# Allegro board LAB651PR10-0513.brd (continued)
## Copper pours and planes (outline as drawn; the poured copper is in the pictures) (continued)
DH_CHG on BOTTOM (solid shape): 43.74,18.65 43.74,17.68 43.57,17.5 43.57,16.51 43.54,16.49 43.34,16.49 43.31,16.51 43.31,17.56 43.21,17.66 43.21,18.67 43.29,18.75 43.64,18.75
DL_1.35V on BOTTOM (solid shape): 88.45,21.01 88.45,20.12 88.32,19.99 87.43,19.99 87.31,20.12 87.31,21.01 87.43,21.14 88.32,21.14
DL_1.35V on BOTTOM (solid shape): 86.04,14.41 86.04,13.39 84.89,12.25 84.77,12.25 84.64,12.37 84.64,13.39 85.78,14.53 85.91,14.53
DL_1.35V on IN1 (solid shape): 86.16,14.41 86.16,14.03 85.4,13.26 85.02,13.26 84.89,13.39 84.89,14.03 85.53,14.66 85.91,14.66
DL_1.35V on IN1 (solid shape): 88.7,21.26 88.7,20.07 88.5,19.87 87.53,19.87 87.31,20.1 87.31,21.26 87.43,21.39 88.58,21.39
DL_CHG on TOP (solid shape): 36.63,23.42 36.63,22.28 36.51,22.15 35.43,22.15 35.24,22.34 35.24,23.36 35.36,23.49 36.57,23.49
DL_CHG on BOTTOM (solid shape): 40.1,15.83 40.17,15.72 40.28,15.65 40.35,15.58 40.62,15.58 40.74,15.45 41.81,15.45 41.84,15.42 41.84,15.21 41.83,15.2 40.53,15.2 40.51,15.22 38.91,15.22 38.83,15.31 38.83,15.92 38.94,16.03 39.89,16.03
DL_CHG on IN1 (solid shape): 38.71,16.31 39.81,16.31 40.06,16.06 40.06,15.55 39.79,15.28 38.31,15.28 37.58,16.01 37.58,16.44 38.58,16.44
DL_CHG on IN1 (solid shape): 37.65,21.77 37.65,21.39 37.14,20.88 37.01,20.88 36,21.9 34.85,21.9 34.73,22.03 34.73,22.66 34.98,22.92 36.51,22.92
DP_VSSR on TOP (solid shape): 75.49,86.29 75.49,85.42 75.49,85.31 75.49,78.16 75.24,77.91 73.78,77.91 73.46,78.23 73.46,81.46 73.21,81.72 72.45,81.72 72.32,81.59 72.32,81.28 72.29,81.25 72.29,81.18 72.19,81.08 72.12,81.08 72.12,81.11 71.66,81.11 71.56,81.21 71.56,82.22 71.81,82.48 71.81,84.89 72.45,85.53 72.45,86.42 72.56,86.53 73.15,86.53 73.15,86.54 75.24,86.54
EN_PCIE on BOTTOM (solid shape): 76.56,56.65 76.56,56.01 76.76,55.81 77.4,55.81 77.78,55.43 77.78,55.05 77.65,54.92 75.88,54.92 75.37,55.43 74.99,55.43 74.86,55.55 74.86,56.57 74.99,56.7 76.51,56.7
FB on TOP (solid shape): 61.78,120.45 61.78,119.82 61.91,119.69 62.54,119.69 62.67,119.56 62.67,118.22 62.49,118.04 61.27,118.04 61.14,118.17 61.14,120.45 61.27,120.58 61.65,120.58
FB_1.1V on BOTTOM (solid shape): 112.2,4.63 112.2,3.1 111.82,2.72 108.31,2.72 108.22,2.81 108.22,3.36 108.48,3.61 110.55,3.61 110.93,3.99 110.93,4.48 111.2,4.75 112.07,4.75
FB_1.5V on TOP (solid shape): 209.99,12.12 209.99,9.83 209.86,9.71 207.83,9.71 207.57,9.96 207.57,10.47 208.18,11.08 208.2,11.08 208.54,11.41 208.25,11.78 208.21,11.79 208.21,11.87 208.59,12.25 209.86,12.25
GPU_B+ on TOP (solid shape): 71.02,45.52 74.22,45.52 74.67,45.07 74.67,43.05 73.78,42.16 67.18,42.16 66.48,42.85 61.86,42.85 61.7,42.7 60.43,42.7 60.2,42.47 60.2,41.52 60.1,41.42 55.79,41.42 55.68,41.43 55.58,41.42 51.95,41.42 51.49,41.87 51.49,45.45 52.11,46.07 57.13,46.07 57.21,46.16 64.45,46.16 64.7,46.41 64.7,47.17 64.95,47.43 69.12,47.43
GPU_B+ on BOTTOM (solid shape): 66.2,45.92 66.2,44.49 65.69,43.97 57.21,43.97 56.95,44.23 56.95,45.9 57.21,46.16 65.97,46.16
INT-SPK-L+ on TOP (solid shape): 203.92,17.07 203.92,16.02 203.83,15.93 202.24,15.93 202.11,16.06 202.11,16.95 202.32,17.15 203.84,17.15
INT-SPK-L+ on BOTTOM (solid shape): 202.04,20.02 202.04,19.69 201.93,19.58 199.24,19.58 199.24,19.79 200.82,19.79 201.12,20.1 201.96,20.1
INT-SPK-L+ on IN1 (solid shape): 203.54,16.39 202.95,15.8 201.78,15.8 201.61,15.98 201.61,17.1 202.85,18.34 203.54,18.34
INT-SPK-L+ on IN1 (solid shape): 202.37,20.12 202.49,20.12 203,19.61 203,19.23 202.62,18.85 202.37,18.85 201.89,19.33 201.83,19.33 201.81,19.35 201.58,19.46 201.33,19.38 201.26,19.36 201.2,19.38 201.06,19.45 200.91,19.46 200.88,19.45 200.77,19.56 200.77,19.84 200.94,20.07 200.88,20.35 200.86,20.39 201.17,20.71 201.78,20.71
INT-SPK-L- on TOP (solid shape): 206.58,16.92 206.58,15.07 206.47,14.95 205.15,14.95 205.04,15.06 205.04,16.95 205.25,17.16 206.34,17.16
INT-SPK-L- on BOTTOM (solid shape): 201.81,19.31 201.81,18.95 201.73,18.88 200.87,18.88 200.56,19.18 199.33,19.18 199.33,19.39 201.73,19.39
INT-SPK-L- on IN2 (solid shape): 206.91,15.8 206.79,15.68 206.05,15.68 205.9,15.83 205.9,18.01 206.91,18.01
INT-SPK-L- on IN2 (solid shape): 200.92,19.66 201.2,19.51 201.49,19.64 201.51,19.66 201.56,19.66 201.57,19.65 201.81,19.57 202.03,19.66 202.27,19.66 202.47,19.46 202.47,18.88 202.24,18.65 201.91,18.65 201.66,18.82 201.36,18.73 201.29,18.7 201.22,18.73 201.03,18.82 200.81,18.79 200.71,18.79 200.67,18.88 200.67,19.51 200.82,19.66
INT-SPK-R+ on TOP (solid shape): 207.52,17.17 208.76,17.17 208.84,17.09 208.84,16.06 208.72,15.93 207.32,15.93 207.09,16.16 207.09,17.2 207.18,17.29 207.41,17.29
INT-SPK-R+ on BOTTOM (solid shape): 200.78,18.06 201.75,18.06 201.85,17.96 201.85,17.66 201.77,17.58 200.9,17.58 200.09,18.38 199.51,18.38 199.47,18.42 199.47,18.53 199.53,18.59 200.26,18.59
INT-SPK-R+ on IN3 (solid shape): 207.83,17.84 207.83,16.08 207.65,15.9 206.97,15.9 206.81,16.06 206.81,16.97 206.3,17.48 206.3,18.22 207.45,18.22
INT-SPK-R+ on IN3 (solid shape): 203.79,17.53 203.79,16.74 203.74,16.69 203.16,16.69 202.62,17.23 201.68,17.23 201.33,17.58 200.84,17.58 200.74,17.68 200.74,17.99 200.82,18.06 203.26,18.06
INT-SPK-R- on TOP (solid shape): 212.4,16.95 212.4,15.43 212.25,15.28 210.09,15.28 209.86,15.51 209.86,16.95 210.09,17.17 212.17,17.17
INT-SPK-R- on BOTTOM (solid shape): 200.79,18.7 201.78,18.7 201.83,18.64 201.83,18.36 201.71,18.24 200.88,18.24 200.33,18.78 199.46,18.78 199.45,18.8 199.45,18.98 199.46,18.99 200.5,18.99
INT-SPK-R- on IN3 (solid shape): 212.65,17.68 212.65,15.68 212.53,15.55 211.79,15.55 211.64,15.7 211.64,17.78 212.55,17.78
INT-SPK-R- on IN3 (solid shape): 204.43,18.9 203.76,18.24 200.87,18.24 200.74,18.37 200.74,18.6 200.84,18.7 202.06,18.7 203.1,19.74 204.43,19.74
LG_3V on TOP (solid shape): 69.69,19.93 69.69,19.92 70.59,19.03 71.22,19.03 71.29,18.97 71.29,18.9 71.22,18.84 69.93,18.84 68.91,19.85 68.91,20.16 69.04,20.29 69.34,20.29
LG_5V on TOP (solid shape): 63.73,17.38 63.73,16.62 63.68,16.57 63.68,16.06 63.18,15.55 62.54,15.55 62.29,15.8 62.29,16.95 62.3,16.96 62.3,17.42 62.46,17.59 63.52,17.59
LG_5V on TOP (solid shape): 71.29,17.39 71.29,17.25 71.22,17.19 70.84,17.19 70.45,16.79 70.45,16.46 69.9,15.92 69.47,15.92 69.37,16.02 69.37,16.3 69.37,16.32 69.38,16.33 69.42,16.38 69.46,16.44 70.23,17.21 70.22,17.23 70.22,17.33 70.33,17.44 71.24,17.44
LG_5V on IN3 (solid shape): 70.54,16.82 70.54,16.31 69.44,15.21 68.98,15.21 68.57,15.61 69.94,16.97 70.39,16.97
LG_5V on IN3 (solid shape): 63.23,16.7 63.23,16.26 63.81,15.68 63.81,15.42 63.43,15.04 63.05,15.04 62.36,15.73 62.36,16.78 62.44,16.86 63.07,16.86
LG_+1.05VSP on TOP (solid shape): 180.24,45.57 180.24,44.78 180.12,44.66 180.02,44.66 179.79,44.43 179.79,43.74 179.66,43.62 179.33,43.62 179.25,43.69 179.25,45.42 179.56,45.72 180.09,45.72
LG_+1.05VSP on BOTTOM (solid shape): 181.29,51.62 181.29,50.73 181.16,50.6 180.6,50.6 180.35,50.86 180.35,51.54 180.45,51.64 180.8,51.64 180.9,51.74 181.16,51.74
LG_+1.05VSP on IN3 (solid shape): 181.54,51.74 181.54,49.2 180.52,49.2 180.52,51.74 180.78,52 181.29,52
LG_+1.05VSP on IN3 (solid shape): 180.17,43.59 179.91,43.34 179.23,43.34 179,43.57 179,45.19 179.15,45.34 179.15,45.98 180.17,45.98
LG_+1.35VGPUP on TOP (solid shape): 41.51,49.37 41.51,48.78 41.31,48.57 39.88,48.57 39.68,48.77 39.68,49.59 39.81,49.71 41.17,49.71
LGATE1 on TOP (solid shape): 60.38,54.87 60.38,54.16 60.64,53.9 60.64,53.52 60.51,53.4 59.37,53.4 59.11,53.65 59.11,53.9 59.29,54.08 59.59,54.08 59.75,54.23 59.75,54.87 59.85,54.97 60.28,54.97
LGATE1 on BOTTOM (solid shape): 61.4,42.47 61.4,41.46 61.02,41.08 61.02,38.66 60.89,38.66 60.76,38.79 60.76,40.82 60.25,41.33 60.25,42.47 60.38,42.6 61.27,42.6
LGATE1 on IN3 (solid shape): 60.69,53.84 60.69,53.17 60.28,52.76 60,52.76 59.26,53.5 59.26,53.93 59.41,54.08 60.45,54.08
LGATE1 on IN3 (solid shape): 61.22,42.47 61.22,41.43 60.97,41.18 60.64,41.18 60.33,41.48 60.33,42.47 60.51,42.65 61.04,42.65
LGATE2 on TOP (solid shape): 62.79,48.68 62.79,48.24 63.07,47.96 63.07,47.63 62.95,47.5 62.06,47.5 61.91,47.65 61.91,48.62 62.02,48.73 62.74,48.73
LGATE2 on BOTTOM (solid shape): 62.92,42.6 62.92,40.7 62.29,40.06 62.29,38.79 62.16,38.66 62.03,38.79 62.03,40.31 62.29,40.57 62.29,41.46 61.78,41.97 61.78,42.6 61.91,42.73 62.79,42.73
LGATE2 on IN3 (solid shape): 63.07,48.02 63.07,47.35 62.49,46.77 61.4,46.77 61.4,47.66 62.02,48.29 62.81,48.29
LGATE2 on IN3 (solid shape): 62.16,43.67 62.79,43.03 62.79,41.76 62.62,41.58 62.21,41.58 62.03,41.76 62.03,42.68 61.4,43.31 61.4,44.07 61.45,44.12 62.16,44.12
LGATE_APU1 on TOP (solid shape): 68,115.6 68,114.79 67.27,114.05 66.12,114.05 66.12,114.25 66.96,114.25 67.44,114.74 67.44,115.6 67.57,115.73 67.87,115.73
LGATE_APU1 on BOTTOM (solid shape): 88.7,120.2 88.7,119.44 88.58,119.31 86.42,119.31 86.29,119.44 86.29,120.2 86.42,120.32 88.58,120.32
LGATE_APU1 on IN3 (solid shape): 68.21,114.46 68.05,114.3 67.37,114.3 67.19,114.48 67.19,116.82 68.21,116.82
LGATE_APU1 on IN3 (solid shape): 87.56,120.32 88.7,120.32 88.83,120.2 88.83,119.44 88.58,119.18 87.18,119.18 85.78,120.58 85.78,121.34 85.91,121.47 86.42,121.47
LGATE_NB1 on TOP (solid shape): 68.48,112.58 68.48,112.32 68.33,112.17 67.49,112.17 67.21,112.45 66.17,112.45 66.15,112.48 66.15,112.63 66.17,112.65 66.86,112.65 66.91,112.7 68.36,112.7
LGATE_NB1 on BOTTOM (solid shape): 80.96,109.91 80.96,109.15 80.83,109.02 78.8,109.02 78.67,109.15 78.67,109.91 78.8,110.04 80.83,110.04
LGATE_NB1 on IN3 (solid shape): 80.19,109.91 80.96,109.91 81.21,109.66 81.21,109.02 81.08,108.89 79.81,108.89 78.67,110.04 78.67,110.55 79.05,110.93 79.18,110.93
LGATE_NB1 on IN3 (solid shape): 70.8,113.34 70.8,112.6 70.47,112.27 69.22,112.27 68.89,111.94 67.24,111.94 66.99,112.2 66.99,112.7 67.24,112.96 68.38,112.96 68.89,113.47 70.67,113.47
LX_1.1V on BOTTOM (solid shape): 119.94,8.56 119.94,6.53 119.69,6.28 116.52,6.28 115.63,5.39 114.42,5.39 114.23,5.58 114.23,8.12 115.06,8.95 117.9,8.95 118.04,9.08 119.42,9.08
LX_1.5V on TOP (solid shape): 206.43,8.44 206.43,7.8 206.3,7.68 206.3,7.33 206.29,7.33 206.29,7.15 206.18,7.04 206.18,6.28 206.05,6.15 205.26,6.15 205.05,5.94 205.03,5.94 205.03,5.92 204.98,5.87 204.98,4.93 204.83,4.78 203.74,4.78 203.64,4.88 203.64,8.13 204.07,8.56 206.3,8.56
LX_1.8V on BOTTOM (solid shape): 89.97,26.85 89.97,24.06 89.86,23.94 88.77,23.94 88.64,24.07 88.64,24.29 88.23,24.69 87.42,24.69 87.23,24.88 87.23,26.08 86.98,26.34 86.98,26.85 87.1,26.98 88.69,26.98 88.7,26.99 89.84,26.99
LX_3V on TOP (solid shape): 66.96,26.36 66.96,25.96 67.66,25.26 68.19,25.26 68.23,25.23 68.23,23.78 67.75,23.3 63.35,23.3 62.1,24.54 60.46,24.54 60.34,24.66 60.34,26.75 60.56,26.97 66.35,26.97
LX_3V on TOP (solid shape): 73.69,21.73 73.69,21.14 73.52,20.96 73.22,20.96 73.18,20.92 73.18,20.92 73.1,20.84 73.07,20.85 72.73,20.75 72.64,20.41 72.64,20.39 72.37,20.11 72.37,19.16 72.3,19.09 72.24,19.09 72.18,19.16 72.18,20.3 72.05,20.43 72.05,21.32 72.18,21.44 72.18,21.45 72.59,21.86 73.56,21.86
LX_3V on BOTTOM (solid shape): 67.11,25.58 67.11,23.68 65.08,21.65 61.59,21.65 60.61,22.62 60.61,25.94 60.89,26.22 66.48,26.22
LX_3V on IN1 (solid shape): 63.65,25.37 63.65,24.73 64.15,24.22 64.15,24.1 63.73,23.68 63.68,23.68 63.01,24.35 63.01,25.37 63.14,25.49 63.52,25.49
LX_3V on IN1 (solid shape): 72.56,21.63 72.56,20.43 72.43,20.3 72.08,20.3 71.73,20.65 71.73,21.38 71.44,21.67 71.44,21.95 71.7,22.2 71.99,22.2
LX_5V on TOP (solid shape): 72.37,17.07 72.37,15.91 72.56,15.73 72.56,14.94 72.33,14.71 72.33,14.18 72.21,14.05 71.42,14.05 71.3,14.17 71.3,15.04 72.11,15.85 72.11,16.99 72.22,17.1 72.35,17.1
LX_5V on TOP (solid shape): 65.69,15.32 65.69,13.64 65.72,13.62 65.72,13.14 65.21,12.63 65.21,10.14 64.93,9.86 60.86,9.86 59.43,11.29 59.43,14.03 59.56,14.15 61.14,14.15 61.22,14.08 61.22,12.04 61.4,11.87 62.67,11.87 62.85,12.04 62.85,14.84 63.3,15.29 63.3,15.3 63.43,15.42 65.59,15.42
LX_5V on BOTTOM (solid shape): outline of 85 points within 59.37,10.15 67.11,15.55
LX_5V on IN1 (solid shape): 72.81,15.79 72.81,14.39 72.45,14.03 71.89,14.03 71.81,14.11 71.81,15.82 71.97,15.98 72.62,15.98
LX_5V on IN1 (solid shape): 65.84,12.76 65.84,12.12 65.72,11.99 64.57,11.99 64.32,11.74 62.92,11.74 62.79,11.87 62.79,12.7 62.97,12.88 65.72,12.88
LX_CHG on TOP (solid shape): 43.87,29.27 43.87,27.14 44.81,26.2 44.81,24.24 43.11,22.53 37.78,22.53 37.42,22.89 37.42,27.03 38.92,27.03 40.4,28.52 40.4,29.1 40.82,29.52 43.62,29.52
LX_CHG on BOTTOM (solid shape): 43.33,28.68 45.15,28.68 45.29,28.55 45.29,24.5 45.15,24.36 38.44,24.36 38.04,24.76 38.04,28.63 38.49,29.07 42.93,29.07
LX_CHG on BOTTOM (solid shape): 43.14,19.56 43.14,18.88 43.07,18.81 43.07,16.52 42.98,16.44 42.86,16.44 42.82,16.48 42.82,17.32 42.6,17.53 42.42,17.53 42.2,17.76 42.2,19.54 42.25,19.59 43.11,19.59
LX_CHG on IN1 (solid shape): 43.03,17.56 42.75,17.28 42.3,17.28 42.02,17.56 42.02,20.27 43.03,20.27
LX_CHG on IN1 (solid shape): 43.33,25.8 43.33,23.61 43.14,23.42 42.02,23.42 42.02,25.61 42.3,25.89 43.24,25.89
LX_PCIE on TOP (solid shape): 76.64,59.49 76.64,57.36 76.38,57.1 74.53,57.1 74.1,56.67 74.1,56.44 73.84,56.19 71.84,56.19 71.15,56.87 71.15,59.21 71.68,59.75 76.38,59.75
LX_PCIE on BOTTOM (solid shape): 76.49,60.41 76.49,57.74 75.83,57.08 74.35,57.08 74.1,56.82 74.1,55.55 73.97,55.43 72.19,55.43 72.07,55.55 72.07,56.37 71.18,57.26 71.18,60 72.19,61.02 75.88,61.02
MIC_IN on BOTTOM (solid shape): 190.84,33.79 190.92,33.69 191.02,33.63 191.03,33.62 191.19,33.46 191.19,32.69 191.19,32.69 191.19,32.31 191.08,32.2 191.05,32.24 189.62,32.24 189.54,32.31 189.54,33.71 189.62,33.79
MIC_IN on BOTTOM (solid shape): 193.61,19.18 192.59,19.18 192.03,18.62 192.03,18.09 191.67,17.73 191.24,17.73 191.01,17.96 191.01,18.42 191.1,18.57 191.11,18.74 191.11,18.76 191.34,19 191.73,19 192.1,19.38 193.48,19.38 193.61,19.39
MIC_IN on IN1 (solid shape): 192.13,17.94 191.98,17.78 191.24,17.78 191.12,17.91 191.12,20.1 192.13,20.1
MIC_IN on IN1 (solid shape): 191.5,32.52 191.5,32.46 191.48,32.44 191.37,32.18 191.5,31.91 191.5,30.48 191.42,30.41 190.63,30.41 190.48,30.56 190.48,32.57 190.63,32.72 191.29,32.72
MIC_IN_R on BOTTOM (solid shape): 196.53,34.09 196.53,32.69 196.37,32.54 196.04,32.54 195.97,32.62 194.34,32.62 194.16,32.44 191.98,32.44 191.88,32.54 191.45,32.54 191.4,32.59 191.4,33.54 191.36,33.57 191.45,33.66 192.46,33.66 192.82,33.3 192.82,33.28 192.84,33.28 192.89,33.23 193.07,33.23 193.15,33.21 193.22,33.2 194.01,33.2 194.08,33.21 194.19,33.23 194.21,33.25 194.33,33.34 194.42,33.46 194.42,33.46 194.65,33.68 194.65,34.04 194.82,34.22 196.4,34.22
MIC_IN_R on IN1 (solid shape): 197.31,33.2 197.69,33.2 198.05,32.85 198.05,32.16 197.85,31.96 195.56,31.96 194.9,32.62 194.9,34.17 194.93,34.19 196.32,34.19
P2 on TOP (solid shape): 31.91,34.32 31.91,33.13 31.83,33.05 30.62,33.05 30.49,32.92 29.83,32.92 29.72,33.02 29.72,33.53 29.66,33.6 29.66,33.73 29.53,33.73 29.29,33.96 29.29,34.55 29.54,34.8 30.91,34.8 30.92,34.8 31.05,34.78 31.17,34.8 31.18,34.8 31.43,34.8
P2 on BOTTOM (solid shape): 25,37.01 25.36,36.62 25.71,37.01 30.26,37.01 30.56,36.71 30.56,33.46 30.33,33.23 26.92,33.23 26.65,33.36 26.38,33.23 24.54,33.23 24.31,33.46 24.31,36.78 24.54,37.01
P3 on BOTTOM (solid shape): 36.7,38.09 36.7,37.52 35.17,37.52 34.92,37.27 34.92,36.95 35.17,36.69 36.7,36.69 36.7,33.77 36.32,33.39 34.76,33.39 34.52,33.48 34.29,33.39 32.12,33.39 31.81,33.71 31.81,37.84 32.38,38.41 36.38,38.41
PACIN# on TOP (solid shape): 77.78,97.72 77.78,96.83 77.65,96.7 76.13,96.7 76,96.83 76,97.85 76.13,97.97 77.53,97.97
PCIE_B+ on BOTTOM (solid shape): 74.1,53.14 74.1,52.25 74.99,51.36 75.03,51.36 75.04,51.36 75.16,51.34 75.29,51.36 75.3,51.36 75.69,51.36 75.7,51.36 75.83,51.34 75.95,51.36 75.96,51.36 76.13,51.36 76.26,51.49 76.26,52.3 76.56,52.61 78.47,52.61 78.6,52.48 78.6,51.91 78.62,51.91 78.62,51.62 78.6,51.62 78.6,51.11 78.62,51.11 78.62,50.82 78.6,50.82 78.6,50.53 77.4,49.33 73.46,49.33 73.34,49.46 73.34,51.49 73.32,51.5 73.32,51.66 72.83,52.15 72.83,53.14 72.95,53.27 73.97,53.27
PHASE1 on TOP (solid shape): 54.54,55.3 56.19,55.3 56.45,55.05 56.45,46.93 56.14,46.63 53.3,46.63 52.92,47.01 52.92,48.48 52.62,48.78 51.98,48.78 50.71,50.04 50.27,50.04 50.09,50.22 50.09,54.41 51.47,55.78 54.06,55.78
PHASE1 on BOTTOM (solid shape): 60,42.22 60,41.2 60.64,40.57 60.64,38.66 60.56,38.59 60.48,38.59 60.41,38.66 60.41,40.03 59.75,40.7 59.7,40.7 58.98,41.41 58.98,42.22 59.11,42.35 59.87,42.35
PHASE1 on BOTTOM (solid shape): 57.21,54.49 57.21,49.51 56.39,48.7 54.35,48.7 53.63,47.97 53.63,46.22 53.37,45.97 50.81,45.97 50.72,46.03 50.75,46.14 50.88,46.44 50.74,46.74 50.7,46.82 50.74,46.9 50.5,47.58 50.27,46.9 50.31,46.82 50.27,46.74 50.12,46.44 50.25,46.14 50.28,46.03 50.19,45.97 50.16,45.97 49.97,46.16 49.97,54.52 50.35,54.89 55.21,54.89 55.28,54.82 55.28,51.34 55.3,51.31 56.05,51.31 56.08,51.34 56.08,54.82 56.24,54.99 56.71,54.99
PHASE1 on IN1 (solid shape): 51.64,51.41 51.64,50.12 51.5,49.98 51.02,49.98 50.88,50.12 50.88,51.31 51.01,51.44 51.62,51.44
PHASE1 on IN1 (solid shape): 60,41.97 60,41.58 60.64,40.95 60.64,40.42 60.38,40.16 60.15,40.16 59.11,41.2 59.11,41.46 58.86,41.71 58.86,42.09 59.11,42.35 59.62,42.35
PHASE2 on TOP (solid shape): 71.56,54.74 71.56,52.51 71.56,52.5 71.56,50.92 71.87,50.61 73.48,50.61 73.58,50.51 73.58,49.31 73.49,49.22 73.22,49.22 73.21,49.22 71.56,49.22 70.53,48.19 66.35,48.19 66.1,48.44 66.1,49.72 65.6,50.22 64.93,50.22 64.7,50.45 64.7,54.46 65.23,55 71.3,55
PHASE2 on BOTTOM (solid shape): 64.19,42.22 64.19,41.08 63.68,40.57 63.35,40.57 62.67,39.88 62.67,38.66 62.41,38.66 62.41,39.93 63.05,40.57 63.05,42.22 63.18,42.35 64.06,42.35
PHASE2 on BOTTOM (solid shape): 71.3,55.55 71.3,48.92 71.2,48.82 64.46,48.82 64.29,48.99 64.29,49.56 62.76,51.1 62.76,54.84 62.96,55.05 63.76,55.05 63.76,55.04 63.93,54.87 63.93,51.36 63.96,51.33 64.69,51.33 64.71,51.35 64.71,54.89 65.46,55.64 71.22,55.64
PHASE2 on IN1 (solid shape): 64.32,41.58 64.32,41.33 63.56,40.57 63.3,40.57 62.92,40.95 62.92,41.2 63.68,41.97 63.94,41.97
PHASE2 on IN1 (solid shape): 71,49.22 71,48.67 70.87,48.54 69.48,48.54 69.41,48.61 69.41,49.29 69.49,49.37 70.85,49.37
PHASE_APU1 on TOP (solid shape): 69.91,115.65 69.91,114.74 69.78,114.61 68.61,114.61 67.65,113.64 66.17,113.64 66.12,113.69 66.12,113.85 66.15,113.87 67.44,113.87 68.38,114.81 68.38,115.65 68.48,115.75 69.81,115.75
PHASE_APU1 on BOTTOM (solid shape): 81.97,120.2 81.97,119.44 81.84,119.31 79.81,119.31 79.69,119.44 79.69,120.2 79.81,120.32 81.84,120.32
PHASE_APU1 on IN1 (solid shape): 70.26,116.46 70.26,114.96 69.81,114.51 69.3,114.51 69.07,114.74 69.07,116.54 69.17,116.64 70.08,116.64
PHASE_APU1 on IN1 (solid shape): 80.98,120.07 80.98,119.46 80.83,119.31 78.7,119.31 78.44,119.56 78.44,120.1 78.77,120.43 80.63,120.43
PHASE_NB1 on TOP (solid shape): 67.47,112.02 69.78,112.02 69.91,111.89 69.91,111.03 69.75,110.88 68.71,110.88 67.85,111.74 67.44,111.74 67.14,112.04 66.2,112.04 66.17,112.07 66.17,112.22 66.22,112.27 67.21,112.27
PHASE_NB1 on BOTTOM (solid shape): 74.22,111.19 74.22,110.69 74.22,110.69 74.22,109.78 74.22,109.15 74.1,109.02 73.06,109.02 72.97,109.11 72.97,111.21 73.15,111.38 74.03,111.38
PHASE_NB1 on IN1 (solid shape): 74.28,111.84 74.28,110.06 74,109.78 73.72,109.78 73.21,110.29 73.21,111.36 73.36,111.51 73.36,111.87 73.59,112.09 74.02,112.09
PHASE_NB1 on IN1 (solid shape): 70.85,112.5 70.85,111.35 70.35,110.85 69.55,110.85 69.32,111.08 69.32,111.97 69.88,112.53 70.82,112.53
PWR_SRC_ON on TOP (solid shape): 10.98,75.87 10.98,75.24 10.72,74.99 10.62,74.99 10.62,75.01 9.91,75.01 9.91,74.93 9.71,74.73 9.71,73.66 9.51,73.46 8.34,73.46 8.17,73.51 7.99,73.47 7.97,73.46 7.8,73.46 7.68,73.59 7.68,75.24 7.8,75.37 8.31,75.37 8.72,75.77 8.74,75.77 8.96,76 10.85,76
RING2 on BOTTOM (solid shape): 191.06,31.93 191.06,30.92 190.96,30.82 190.35,30.82 190.35,29.95 190.28,29.87 190.07,29.87 189.41,30.54 189.41,30.77 189.41,30.79 189.41,31.81 189.64,32.03 190.96,32.03
RING2 on BOTTOM (solid shape): 193.77,18.78 193.23,18.78 193.16,18.71 193.13,18.71 192.93,18.59 192.95,18.35 192.97,18.29 192.9,18.09 192.97,17.89 192.95,17.82 192.92,17.76 192.9,17.69 192.87,17.62 192.8,17.59 192.69,17.59 192.58,17.48 192.41,17.48 192.16,17.73 192.16,17.93 192.23,18 192.23,18.54 192.68,18.98 193.77,18.98
RING2 on IN2 (solid shape): 193.43,19.61 193.43,19.03 193.15,18.75 193.15,17.66 192.97,17.48 192.28,17.48 192.08,17.68 192.08,19.23 192.51,19.66 193.38,19.66
RING2 on IN2 (solid shape): 190.66,32.37 190.91,32.07 191.28,32.18 191.32,32.21 191.37,32.16 191.37,30.08 191.06,29.77 189.97,29.77 189.82,29.93 189.82,29.94 189.74,30.13 189.58,30.24 189.54,30.25 189.54,31.78 190.18,32.41 190.66,32.41
RING2_R on TOP (solid shape): 200.01,38.46 200.39,38.46 200.4,38.45 200.58,38.39 200.77,38.37 202.57,38.37 202.76,38.39 202.94,38.45 202.95,38.46 203.13,38.46 203.16,38.49 204.04,38.49 204.22,38.31 204.22,37.47 203.92,37.17 202.77,37.17 202.54,37.43 202.2,37.53 201.29,37.53 200.95,37.43 200.72,37.16 200.11,37.16 199.07,36.12 199.07,31.25 198.33,30.51 195.74,30.51 195.61,30.64 195.61,31.68 195.94,32.01 196.45,32.01 197.72,33.28 197.72,33.69 197.8,33.94 197.72,34.19 197.72,36.55 199.65,38.49 199.98,38.49
RING2_R on BOTTOM (solid shape): 195.08,31.83 196.41,31.83 196.46,31.76 196.53,31.7 196.53,30.74 196.4,30.61 196.04,30.61 195.94,30.71 194.65,30.71 194.44,30.92 194.43,30.94 194.4,31.03 194.35,31.11 194.34,31.13 194.34,31.2 194.27,31.27 194.14,31.27 194.06,31.29 193.99,31.3 193.22,31.3 193.15,31.29 193.07,31.27 192.84,31.27 192.46,30.89 191.4,30.89 191.29,30.99 191.29,31.75 191.37,31.83 191.9,31.83 192.25,32.17 193.44,32.17 193.45,32.19 194.72,32.19
SNUB_PCIE on TOP (solid shape): 76.64,56.48 76.64,54.7 76.51,54.58 76.24,54.58 76.12,54.7 76.12,55.31 75.88,55.55 74.73,55.55 74.61,55.68 74.61,56.57 74.76,56.72 75.09,56.72 75.1,56.74 76.38,56.74
SPK_L1-_CONN on TOP (solid shape): 206.43,20.25 206.43,17.96 206.01,17.54 205.07,17.54 204.91,17.71 204.91,18.22 205.29,18.6 205.29,19.61 205.03,19.87 205.03,20.25 205.29,20.5 206.18,20.5
SPK_L1-_CONN on BOTTOM (solid shape): 206.18,20.25 206.18,18.72 206.05,18.6 206.05,15.93 206.56,15.42 206.56,13.39 206.3,13.14 205.92,13.14 205.67,13.39 205.67,15.04 205.03,15.68 205.03,18.09 204.78,18.34 204.78,20.12 205.03,20.38 206.05,20.38
SPK_L2+_CONN on TOP (solid shape): 204.02,20.25 204.02,18.6 203.89,18.47 203.89,17.64 203.8,17.56 202.98,17.56 202.88,17.66 202.88,18.34 203.13,18.6 203.13,19.49 202.88,19.74 202.88,20.25 203,20.38 203.89,20.38
SPK_L2+_CONN on BOTTOM (solid shape): 204.02,20.2 204.02,18.47 203.76,18.22 203.76,15.68 204.4,15.04 205.03,15.04 205.29,14.79 205.29,13.39 205.03,13.14 204.65,13.14 202.75,15.04 202.75,20.04 203.07,20.36 203.86,20.36
SPK_R1-_CONN on TOP (solid shape): 212.27,20.12 212.27,18.22 211.63,17.57 210,17.57 209.86,17.71 209.86,18.34 209.99,18.47 210.11,18.47 210.24,18.6 210.24,20.12 210.5,20.38 212.02,20.38
SPK_R1-_CONN on BOTTOM (solid shape): 211.64,20.12 211.64,15.93 208.84,13.14 208.34,13.14 208.21,13.26 208.21,14.79 208.59,15.17 209.1,15.17 210.24,16.31 210.24,18.09 209.86,18.47 209.86,20.12 210.11,20.38 211.38,20.38
SPK_R2+_CONN on TOP (solid shape): 208.34,20.24 208.34,19.37 208.34,19.36 208.34,18.6 208.46,18.47 208.59,18.47 208.72,18.34 208.72,17.68 208.59,17.56 207.88,17.56 207.07,18.37 207.07,20.25 207.19,20.38 208.2,20.38
SPK_R2+_CONN on BOTTOM (solid shape): 209.1,19.61 209.1,17.96 208.72,17.58 208.72,15.68 207.83,14.79 207.83,13.39 207.57,13.14 207.19,13.14 206.94,13.39 206.94,15.42 207.7,16.18 207.7,17.71 207.07,18.34 207.07,20.25 207.19,20.38 208.34,20.38
SW_1.35V on BOTTOM (solid shape): 87.81,13.52 87.81,12.76 87.69,12.63 87.43,12.63 86.67,11.87 85.15,11.87 85.15,12.25 85.65,12.25 87.05,13.64 87.69,13.64
SW_1.35V on BOTTOM (solid shape): 94.8,20.63 94.8,16.82 93.4,15.42 92.64,15.42 92.21,14.99 90.4,14.99 90.4,14.99 90.36,14.99 90.04,15.31 90.04,17.08 89.03,18.09 89.03,21.98 89.21,22.15 93.27,22.15
SW_1.35V on IN1 (solid shape): 91.52,17.63 91.52,16.59 86.8,11.87 86.29,11.87 86.16,11.99 86.16,13.52 86.35,13.71 87.06,13.71 90.33,16.97 90.33,17.35 90.73,17.76 91.4,17.76
SW_+1.05VSP on TOP (solid shape): 178.87,44.63 178.87,43.62 179.13,43.36 179.76,43.36 179.91,43.51 179.91,44.05 184.54,44.05 184.97,43.62 184.97,41.33 182.45,38.82 174.66,38.82 174.17,39.3 174.17,42.47 174.55,42.85 176.84,42.85 176.97,42.73 176.97,41.97 176.21,41.2 176.21,40.19 176.46,39.93 177.35,39.93 177.86,40.44 177.86,42.85 177.73,42.98 177.73,44.63 177.86,44.76 178.75,44.76
SW_+1.05VSP on BOTTOM (solid shape): 180.02,47.17 180.02,45.01 179.89,44.89 179.25,44.89 179,44.63 179,43.24 178.85,43.08 177.17,43.08 176.97,43.29 176.97,47.05 177.22,47.3 179.89,47.3
SW_+1.05VSP on BOTTOM (solid shape): 179.63,51.44 179.63,50.6 179.81,50.42 179.81,48.44 179.71,48.34 179.03,48.34 179,48.37 179,49.2 179.3,49.51 179.3,50.42 179.36,50.47 179.36,51.46 179.38,51.49 179.58,51.49
SW_+1.05VSP on IN1 (solid shape): 180.07,50.7 180.07,48.75 179.99,48.67 179.1,48.67 179.05,48.72 179.05,50.7 179.18,50.83 179.94,50.83
SW_+1.05VSP on IN1 (solid shape): 179.13,45.34 179,45.22 179,43.87 178.75,43.62 178.49,43.62 178.36,43.74 178.36,44.76 178.11,45.01 178.11,46.36 179.13,46.36
SW_+1.35VGPUP on TOP (solid shape): 37.3,51.33 37.31,51.32 37.4,51.16 37.55,51.07 37.56,51.07 37.78,50.86 37.78,50.35 39.17,48.95 39.17,46.74 39.4,46.51 41.1,46.51 41.48,46.13 41.48,44.91 41.2,44.63 37.27,44.63 36.99,44.91 36.99,46.05 36.63,46.41 36.63,47.83 35.62,48.84 35.62,51.36 36,51.74 36.89,51.74
SW_+1.35VGPUP on BOTTOM (solid shape): 41.33,46.03 41.33,43.49 40.7,42.85 37.01,42.85 36.63,43.24 36.63,45.14 36.38,45.39 35.36,45.39 34.53,46.23 33.02,46.23 32.95,46.3 32.95,46.47 33.01,46.54 36.25,46.54 36.63,46.92 36.63,47.55 37.27,48.19 39.17,48.19
UG_3V on TOP (solid shape): 60.1,25.48 60.1,24.72 59.91,24.53 59.18,24.53 59.09,24.63 59.09,25.54 59.21,25.67 59.91,25.67
UG_3V on TOP (solid shape): 70.97,20.11 71.48,20.11 71.48,20.11 71.53,20.11 71.58,20.06 71.58,19.14 71.53,19.09 71.43,19.09 71.37,19.16 70.84,19.16 70.06,19.94 70.06,20.21 70.33,20.49 70.59,20.49
UG_3V on IN1 (solid shape): 71.3,19.74 71.3,19.36 71.18,19.23 70.41,19.23 68.89,20.76 68.89,21.01 69.27,21.39 69.65,21.39
UG_3V on IN1 (solid shape): 59.91,25.68 59.91,23.71 59.75,23.55 58.98,23.55 58.83,23.71 58.83,25.74 59.02,25.93 59.65,25.93
UG_5V on TOP (solid shape): 71.63,17.06 71.63,16.17 71.19,15.73 70.87,15.73 70.7,15.9 70.7,16.85 70.91,17.06 71.28,17.06 71.35,17.14 71.56,17.14
UG_5V on TOP (solid shape): 62.67,13.9 62.67,12.25 62.54,12.12 61.55,12.12 61.44,12.23 61.44,13.94 61.52,14.03 62.54,14.03
UG_5V on IN1 (solid shape): 71.35,16.74 71.35,15.41 70.87,14.93 70.75,14.93 70.51,15.16 70.51,15.84 70.72,16.04 70.72,16.93 70.78,17 71.1,17
UG_5V on IN1 (solid shape): 62.95,13.34 62.95,13.14 62.67,12.86 62.67,12.25 62.54,12.12 62.36,12.12 62.36,12.12 61.73,12.12 61.72,12.12 61.58,12.12 61.47,12.22 61.47,13.39 61.72,13.64 62.65,13.64
UG_+1.05VSP on TOP (solid shape): 177.62,42.75 177.62,40.61 177.2,40.19 176.54,40.19 176.43,40.29 176.43,41.18 177.22,41.96 177.22,42.54 177.21,42.54 177.21,42.77 177.26,42.82 177.55,42.82
UG_+1.05VSP on BOTTOM (solid shape): 179.13,51.46 179.13,50.78 179.15,50.75 179.15,49.56 179,49.41 178.47,49.41 178.29,49.59 178.29,50.45 178.44,50.6 178.64,50.6 178.85,50.8 178.85,51.44 178.9,51.49 179.1,51.49
UG_+1.05VSP on IN1 (solid shape): 177.2,41.76 177.2,40.19 176.92,39.91 176.49,39.91 175.39,41 175.39,42.35 175.72,42.68 176.28,42.68
UG_+1.05VSP on IN1 (solid shape): 178.82,50.55 178.82,49.2 178.01,48.39 177.6,48.39 177.32,48.67 177.32,49.13 177.81,49.61 177.81,50.55 177.91,50.65 178.72,50.65
UG_+1.35VGPUP on TOP (solid shape): 36.74,45.84 36.74,45.03 36.59,44.89 34.35,44.89 33.99,45.25 33.99,45.88 34.14,46.03 36.55,46.03
UG_+1.35VGPUP on BOTTOM (solid shape): 34.85,45.52 34.85,45.14 34.6,44.89 34.35,44.89 34.09,45.14 34.09,45.39 33.77,45.71 33.04,45.71 32.95,45.8 32.95,45.91 33.07,46.03 34.35,46.03
UGATE1 on TOP (solid shape): 50.98,48.06 50.98,46.28 50.73,46.03 50.22,46.03 49.97,46.28 49.97,48.19 50.09,48.32 50.73,48.32
UGATE1 on BOTTOM (solid shape): 60.25,39.93 60.25,38.66 60.18,38.59 60.08,38.59 60,38.66 60,39.81 59.87,39.93 59.37,39.93 58.48,40.82 58.48,41.08 58.6,41.2 58.98,41.2
UGATE1 on IN1 (solid shape): 51.06,47.76 51.06,46.05 51.01,46 50.39,46 50.12,46.27 50.12,47.76 50.2,47.83 50.98,47.83
UGATE1 on IN1 (solid shape): 58.98,41.33 58.98,41.08 59.49,40.57 59.49,40.31 59.34,40.16 58.83,40.16 57.84,41.15 57.84,41.46 58.22,41.84 58.48,41.84
UGATE2 on TOP (solid shape): 64.95,47.91 64.95,47.61 64.85,47.5 64.22,47.5 64.22,47.5 63.79,47.5 63.63,47.65 63.63,47.93 63.44,48.12 63.44,48.66 63.48,48.7 64.17,48.7
UGATE2 on BOTTOM (solid shape): 65,40.72 65,40.44 64.42,39.86 64.01,39.86 63.96,39.91 63.3,39.91 63.05,39.65 63.05,38.64 63,38.59 62.85,38.59 62.79,38.64 62.79,39.76 63.43,40.39 63.79,40.39 64.32,40.92 64.8,40.92
UGATE2 on IN3 (solid shape): 65.72,41.74 65.72,41.08 64.4,39.76 64.04,39.76 63.73,40.06 63.73,40.21 64.6,41.08 64.6,41.2 65.23,41.84 65.61,41.84
UGATE_APU1 on TOP (solid shape): 69.35,114.36 69.35,113.52 69.25,113.42 68.51,113.42 68.36,113.26 66.2,113.26 66.17,113.29 66.17,113.44 66.2,113.47 67.67,113.47 68.64,114.43 69.27,114.43
UGATE_NB1 on TOP (solid shape): 67.37,111.61 67.7,111.61 68.56,110.75 69.2,110.75 69.3,110.65 69.3,109.73 69.27,109.71 68.64,109.71 68.61,109.73 68.61,110.34 67.6,111.36 67.32,111.36 67.04,111.64 66.2,111.64 66.17,111.66 66.17,111.84 66.2,111.87 67.11,111.87
N3691692 on BOTTOM (solid shape): 178.24,49.33 178.24,48.32 178.11,48.19 176.71,48.19 176.21,48.7 176.21,49.71 176.33,49.84 177.73,49.84
N16955074 on TOP (solid shape): 59.49,54.79 59.49,54.26 59.44,54.21 58.87,54.21 58.65,53.99 58.65,52.95 58.31,52.62 57.36,52.62 57.11,52.87 57.11,54.79 57.26,54.94 59.34,54.94
N16955100 on BOTTOM (solid shape): 55.52,47.96 55.52,46.8 55.75,46.58 56.64,46.58 56.7,46.51 56.7,45.81 56.65,45.76 54.59,45.76 54.27,46.08 54.27,48.07 54.31,48.11 55.37,48.11
N16955117 on BOTTOM (solid shape): 60,43.46 60,42.83 59.92,42.75 57.49,42.75 57.36,42.88 57.36,43.49 57.41,43.54 59.92,43.54
N16955207 on TOP (solid shape): 52.07,48.44 52.51,48.44 52.61,48.34 52.61,46.63 52.49,46.52 51.85,46.52 51.29,47.08 51.29,48.01 50.73,48.57 50.22,48.57 50.09,48.7 50.09,49.33 50.35,49.59 50.92,49.59
N17087943 on BOTTOM (solid shape): 64.9,36.43 64.9,35.64 64.79,35.53 63.56,35.53 63.43,35.66 63.43,36.4 63.56,36.53 64.8,36.53
N17089248 on BOTTOM (solid shape): 65.33,38.16 65.33,37.78 65.28,37.69 65.18,37.69 65.08,37.74 64.97,37.75 64.7,37.75 64.51,37.55 64.49,37.52 63.56,37.52 63.43,37.65 63.43,38.03 63.56,38.16 64.83,38.16 64.95,38.28 65.21,38.28
N17283470 on TOP (solid shape): 91.4,14 91.4,13.69 90.28,12.58 89.34,12.58 89.31,12.6 89.31,13.31 90.2,14.2 91.19,14.2
N17283470 on BOTTOM (solid shape): 91.37,14.66 91.37,13.64 91.24,13.52 90.1,13.52 89.97,13.64 89.97,14.53 90.23,14.79 91.24,14.79
N17706108 on TOP (solid shape): 71.3,110.67 71.3,109.66 71.23,109.58 70.11,109.58 69.91,109.78 69.91,110.55 70.08,110.72 71.25,110.72
N17706108 on BOTTOM (solid shape): 74.22,108.68 74.22,108.39 74.22,108.39 74.22,107.75 74.1,107.62 72.63,107.62 72.51,107.74 72.51,108.74 72.6,108.82 74.08,108.82
N17706108 on IN1 (solid shape): 73.37,109.59 73.37,107.79 73.2,107.62 72.67,107.62 72.37,107.92 72.37,109.71 72.55,109.88 73.08,109.88
N17706108 on IN1 (solid shape): 71.65,110.63 71.65,109.86 71.34,109.55 70.79,109.55 70.63,109.72 70.63,110.7 70.76,110.84 71.44,110.84
N17706210 on TOP (solid shape): outline of 154 points within 78.67,102.32 95.31,111.56
N17706210 on BOTTOM (solid shape): outline of 161 points within 78.67,102.04 95.56,111.56
N17706210 on IN1 (solid shape): outline of 133 points within 78.67,102.56 95.31,111.56
N17706210 on IN2 (solid shape): outline of 133 points within 78.67,102.54 95.31,111.56
N17706210 on IN3 (solid shape): outline of 133 points within 78.67,102.93 95.31,111.56
N17706708 on TOP (solid shape): 92.26,118.17 92.26,112.96 92.13,112.83 90.48,112.83 90.35,112.96 90.35,114.48 90.1,114.74 86.8,114.74 86.67,114.86 86.67,118.17 86.92,118.42 92,118.42
N17706708 on BOTTOM (solid shape): 92.13,118.55 92.13,117.53 89.72,117.53 89.72,116.51 92.13,116.51 92.13,113.72 91.75,113.34 86.8,113.34 86.29,113.85 86.29,118.55 86.54,118.8 91.88,118.8
N17706708 on IN1 (solid shape): 92.13,118.29 92.13,115.12 91.75,114.74 86.8,114.74 86.67,114.86 86.67,117.66 87.69,118.67 91.75,118.67
N17706708 on IN2 (solid shape): 92.13,118.55 92.13,115.12 91.75,114.74 86.8,114.74 86.67,114.86 86.67,118.55 87.05,118.93 91.75,118.93
N17706708 on IN3 (solid shape): 92.13,118.42 92.13,115.12 91.75,114.74 86.8,114.74 86.67,114.86 86.67,118.42 87.05,118.8 91.75,118.8
N17933209 on TOP (solid shape): 63.96,50.89 63.96,50.34 63.82,50.2 63.38,50.2 62.91,49.73 62.91,49.24 62.75,49.08 62.15,49.08 61.93,49.29 61.93,50.1 61.86,50.17 61.86,50.65 62.19,50.98 63.87,50.98
N17933219 on TOP (solid shape): 74.86,48.7 74.86,47.92 74.78,47.85 74.09,47.85 73.51,47.27 73.51,46.58 73.42,46.49 71.81,46.49 71.7,46.6 71.7,47.9 71.76,47.96 72.99,47.96 73.83,48.8 74.76,48.8
N17933234 on BOTTOM (solid shape): 65.72,43.62 65.72,42.98 65.59,42.85 63.18,42.85 63.05,42.98 63.05,43.62 63.18,43.74 65.59,43.74
N17933249 on TOP (solid shape): 65.72,49.38 65.72,48.29 65.59,48.16 65.06,48.16 64.67,48.54 64.67,48.9 64.55,49.03 63.48,49.03 63.4,49.1 63.4,49.59 63.51,49.69 63.51,49.69 63.58,49.76 65.34,49.76
N18296224 on TOP (solid shape): 23.22,116.31 23.22,115.7 25.08,113.85 28.34,113.85 28.43,113.76 28.43,111.78 28.31,111.66 24.03,111.66 22.23,113.47 20.15,113.47 19.74,113.87 19.74,116.44 20.22,116.92 22.61,116.92
N18386729 on BOTTOM (solid shape): 85.58,26.79 85.58,23.4 85.44,23.26 83.03,23.26 82.47,23.82 82.47,24.38 83.04,24.38 83.04,25.77 82.47,25.77 82.47,26.34 82.66,26.53 83.55,26.53 83.99,26.98 85.39,26.98
N18406275 on BOTTOM (solid shape): 111.08,9.66 111.08,7.45 111.51,7.01 112.05,7.01 112.32,6.74 112.32,5.9 112.2,5.77 112.15,5.77 112.13,5.78 112.07,5.8 112.01,5.81 111.37,5.81 111.32,5.8 111.26,5.78 110.31,5.78 110.3,5.77 109.78,5.77 109.66,5.9 109.66,6.66 109.4,6.91 106.86,6.91 106.74,7.04 106.74,9.2 109.63,9.2 109.86,9.42 109.87,9.43 109.99,9.51 110.06,9.63 110.07,9.64 110.09,9.66 110.09,9.73 110.14,9.78 110.95,9.78
N18414408 on TOP (solid shape): 210.37,8.31 210.37,7.97 210.35,7.97 210.35,7.47 210.37,7.47 210.37,7.17 210.35,7.17 210.35,6.67 210.37,6.67 210.37,6.15 210.24,6.02 207.7,6.02 207.45,6.28 207.45,8.18 207.83,8.56 210.11,8.56
N18423379 on TOP (solid shape): 71.3,114.48 71.3,113.59 71.18,113.47 70.03,113.47 69.91,113.59 69.91,114.36 70.16,114.61 71.18,114.61
N18423379 on BOTTOM (solid shape): 81.97,118.8 81.97,118.04 81.84,117.91 79.81,117.91 79.69,118.04 79.69,118.8 79.81,118.93 81.84,118.93
N18423379 on IN1 (solid shape): 72.14,115.14 72.14,113.95 71.41,113.21 70.62,113.21 70.26,113.57 70.26,114.53 71.25,115.52 71.76,115.52
N18423379 on IN1 (solid shape): 81.06,118.6 81.06,117.99 80.78,117.71 78.34,117.71 78.19,117.86 78.19,118.75 78.31,118.88 80.78,118.88
N18432502 on TOP (solid shape): 98.99,31.55 98.99,31.04 98.48,31.04 98.48,29.01 98.99,29.01 98.99,28.5 98.86,28.38 95.43,28.38 95.18,28.63 95.18,32.06 95.43,32.31 98.23,32.31
N18432502 on TOP (solid shape): 97.59,63.94 97.59,63.05 98.48,62.16 98.48,57.97 97.47,56.95 94.16,56.95 93.78,57.33 93.78,58.98 93.91,59.11 94.54,59.11 95.05,59.62 95.05,63.17 95.18,63.3 95.69,63.3 95.89,63.5 95.9,63.5 95.9,63.52 95.94,63.56 95.94,64.06 96.07,64.19 97.34,64.19
N18432502 on IN3 (solid shape): outline of 928 points within 86.8,30.66 102.55,63.68
N19142937 on TOP (solid shape): 32.19,32.82 32.19,30.79 31.81,30.41 29.39,30.41 28.99,30.81 28.99,30.86 28.94,30.86 28.76,31.04 27.23,31.04 26.47,31.81 26.47,31.93 26.83,32.29 26.97,32.29 27.25,32.57 28.12,32.57 28.2,32.54 28.22,32.47 28.66,32.12 28.9,32.62 28.88,32.65 29.05,32.82 30.54,32.82 30.66,32.95 32.06,32.95
N19605393 on TOP (solid shape): 152.76,23.99 152.76,22.59 152.57,22.4 152.43,22.4 152.43,22.41 151.55,22.41 151.42,22.53 151.42,22.74 151.12,23.04 150.6,23.04 150.58,23.02 149.87,23.02 149.85,23.04 149.85,23.52 149.87,23.55 150.26,23.55 150.27,23.55 150.49,23.55 150.62,23.68 150.62,23.91 150.83,24.12 152.63,24.12
N19634132 on TOP (solid shape): 14.6,98.92 14.6,96.96 14.41,96.77 13.77,96.77 13.66,96.88 13.66,97.71 13.26,98.1 12.57,98.1 12.38,98.29 12.38,98.86 12.6,99.09 14.43,99.09
N21178712 on TOP (solid shape): 35.74,111.18 35.74,108.64 35.49,108.39 33.75,108.39 33.58,108.55 33.58,109.28 33.33,109.53 32.19,109.53 32.06,109.66 32.06,111.18 32.26,111.38 35.55,111.38
N29841026 on TOP (solid shape): 21.44,34.68 21.44,33.48 21.32,33.35 18.75,33.35 18.68,33.43 18.68,34.47 18.98,34.78 21.34,34.78
N47008006 on TOP (solid shape): 32,108.27 32.18,108.27 32.19,108.26 33.19,108.26 33.29,108.16 33.29,107.04 33.11,106.86 30.92,106.86 30.79,106.99 30.79,108.89 30.92,109.02 31.25,109.02
N47415217 on TOP (solid shape): 72.66,23.21 73.65,23.21 73.71,23.14 73.71,22.55 73.57,22.41 71,22.41 70.81,22.6 70.81,23.08 70.95,23.22 72.65,23.22
N47415272 on TOP (solid shape): 68,14.15 68,10.22 67.64,9.85 65.81,9.85 65.56,10.11 65.56,12.6 66.3,13.34 66.3,13.98 66.6,14.28 67.87,14.28
N47415370 on TOP (solid shape): 72.38,13.3 72.38,12.76 72.12,12.51 70.27,12.51 70.02,12.76 70.02,13.33 70.19,13.5 72.19,13.5
N47420895 on BOTTOM (solid shape): 88.7,22.33 88.7,21.52 88.58,21.39 87.18,21.39 86.8,21.01 86.8,20.03 86.64,19.87 85.62,19.87 85.53,19.96 85.53,21.52 85.78,21.77 86.06,21.77 86.82,22.53 88.51,22.53

Small or netless copper shapes (teardrops, artwork), in the pictures only: 18 on TOP, 24 on BOTTOM, 1 on IN1

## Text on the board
Ref Des/Silkscreen Bottom: H18 | H17 | H19
User.Comments: LA-B651P | 2014-05-16 | 2015-05-16 | Lily_tang | ZAMB0/ZAMC0 | 1.0
BODY_CENTER: trace Width | Width/Space | SB_1_0mm-8L(4mil & 5mil 50ohm)_130923.pdf | 8.5 | 10 | 8 | 7.2 | 6.7 | 5.5 | 6.5 | 5 | 4.5 | 5.3 | 4 | 6.7/4.3 | 6.5/8 | 6.5/4 | 5/4 | 6/4 | 5.5/4.5 | 5.3/4.3 | 4.5/3.5 | 4/4.5 | 4.5/4.8 | 5.3/6 | 4/6.5 | 100 ohm | 4/12
COMPVAL_TYPE_TOP: FIGURE | SIZE | 8.0 | 10.0 | 22.0 | 28.0 | 37.0 | 47.0 | 110.0 | 130.0 | 142.0 | 43.0 | 63.0 | 71.0 | 59.0x24.0 | 63.0x35.0 | 71.0x31.0 | 87.0x24.0 | 102.0x31.0 | 110.0x39.0 | 130.0x110.0 | 189.0x110.0 | DRILL CHART: TOP to BOTTOM | ALL UNITS ARE IN MILS | TOLERANCE | +3.0/-3.0 | +2.0/-2.0 | PLATED | NON-PLATED | QTY | 3414 | 1551 | 19 | 18 | 8 | 9 | 10 | 3 | 4 | 2 | 7 | 1
User.29: 191.65 | 182.90 | 5.11 | 2.30 | 0.85 | 0.00 | 118.80 | 4.00 | 16.82 | 29.10 | 57.05 | 75.25 | 81.90 | 94.25 | 102.00 | 6.50 | 58.55 | 60.50 | 204.40 | 183.75 | 112.65 | 84.10 | 2.65 | 10.00
User.30: 0.00
User.31: 182.30 | 176.60 | 8.00 | 118.07 | 89.30 | 44.30 | 22.67 | 8.90 | 6.00 | 0.00 | 11.40 | 22.40 | 27.45 | 36.80 | 49.00 | 86.70 | 114.80 | 11.97 | 26.70 | 58.23 | 61.00 | 109.00 | 115.30 | 182.60 | 162.73 | 121.60 | 103.40 | 38.60 | 21.40 | 9.40
User.33: 19.80 | 46.75 | 74.85 | 108.70 | 202.65 | 140.40 | 68.50 | 31.93 | 0.00 | 197.35 | 178.75 | 176.20 | 108.25 | 23.69 | 4.20 | 71.10 | 104.75 | 106.30
User.34: 0.00
User.35: {\Fgdt;n}\Ftxt;8.00 | {\Fgdt;n}\Ftxt;2.80 | {\Fgdt;n}\Ftxt;3.30 | {\Fgdt;n}\Ftxt;6.00 | R3.00 | {\Fgdt;n}\Ftxt;7.00 | {\Fgdt;n}\Ftxt;3.60 | {\Fgdt;n}\Ftxt;9.00 | {\Fgdt;n}\Ftxt;8.55 | 5.50
User.37: 122.80 | 214.40
User.38: 191.65 | 182.90 | 5.11 | 2.30 | 0.85 | 0.00 | 118.80 | 4.00 | 16.82 | 29.10 | 57.05 | 75.25 | 81.90 | 94.25 | 102.00 | 6.50 | 58.55 | 60.50 | 204.40 | 183.75 | 112.65 | 84.10 | 2.65 | 10.00
User.39: 0.00
User.40: 182.30 | 176.60 | 8.00 | 118.07 | 89.30 | 44.30 | 22.67 | 8.90 | 6.00 | 0.00 | 11.40 | 22.40 | 27.45 | 36.80 | 49.00 | 86.70 | 114.80 | 11.97 | 26.70 | 58.23 | 61.00 | 109.00 | 115.30 | 182.60 | 162.73 | 121.60 | 103.40 | 38.60 | 21.40 | 9.40
User.42: 19.80 | 46.75 | 74.85 | 108.70 | 202.65 | 140.40 | 68.50 | 31.93 | 0.00 | 197.35 | 178.75 | 176.20 | 108.25 | 23.69 | 4.20 | 71.10 | 104.75 | 106.30
User.43: 0.00
User.44: {\Fgdt;n}\Ftxt;8.00 | {\Fgdt;n}\Ftxt;2.80 | {\Fgdt;n}\Ftxt;3.30 | {\Fgdt;n}\Ftxt;6.00 | R3.00 | {\Fgdt;n}\Ftxt;7.00 | {\Fgdt;n}\Ftxt;3.60 | {\Fgdt;n}\Ftxt;9.00 | {\Fgdt;n}\Ftxt;8.55 | 5.50
